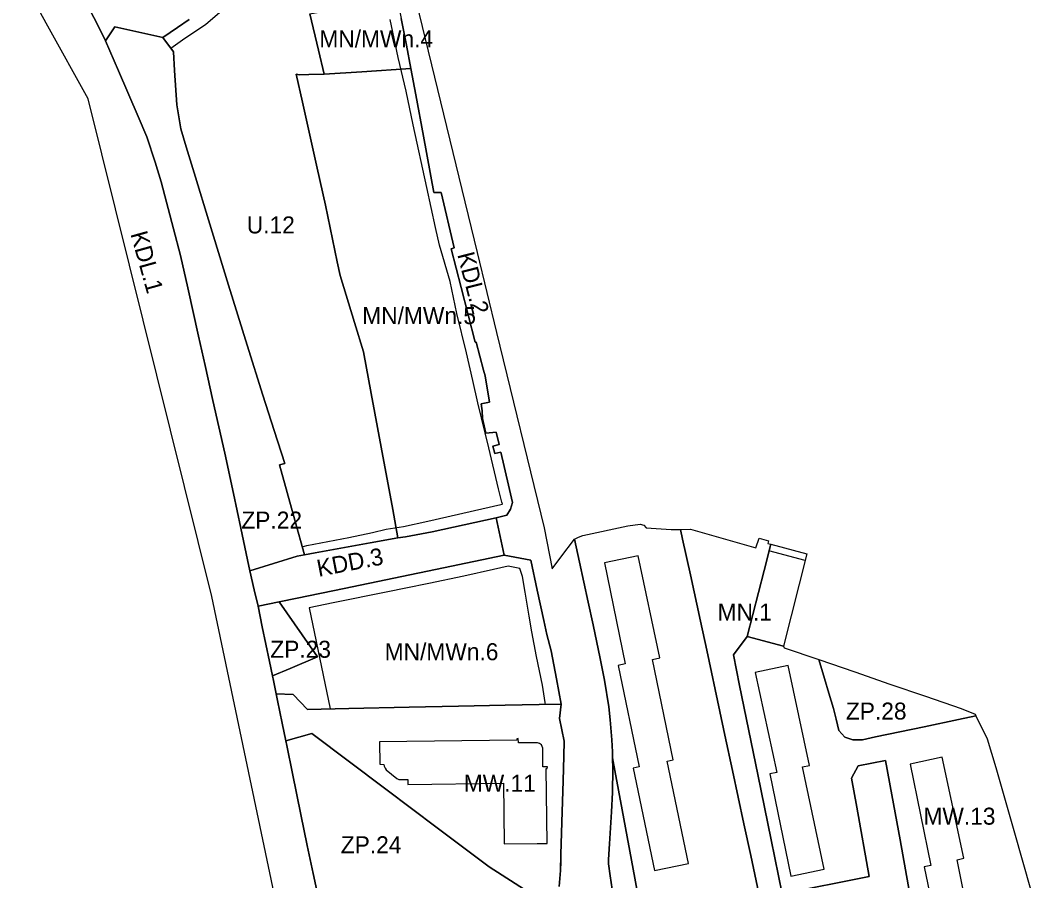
# Model space of a CAD drawing. Extents: x 7429178 to 7430831, y 5550228 to 5551611.
# Drawn here: x 7430377.4 to 7430676.9, y 5550503.4 to 5550756.2 of the extents above; entities that cross this region are included whole.
import ezdxf

# ---------------------------------------------------------------- set-up
doc = ezdxf.new("R2010")
doc.units = 0
for name, color, linetype in [('linie rozgraniczające', 7, 'Continuous'), ('nieprzekraczalne linie zabudowy', 7, 'Continuous'), ('obowiazujace linie zabudowy', 7, 'Continuous'), ('przeznaczenia terenów', 7, 'Continuous')]:
    doc.layers.add(name, color=color, linetype=linetype)

msp = doc.modelspace()

# ---------------------------------------------------------------- linework, layer by layer
at = {"layer": 'linie rozgraniczające'}
for points in [[(7430478.4, 5550824.47), (7430511.65, 5550687.91), (7430517.35, 5550664.42), (7430531.31, 5550607.07), (7430533.69, 5550595), (7430536.22, 5550598.38), (7430540.21, 5550603.72), (7430541.68, 5550596.95), (7430544.25, 5550585.16), (7430545.68, 5550578.56), (7430547.8, 5550568.63), (7430549.01, 5550562.26), (7430550.3, 5550554.42), (7430550.7, 5550550.58), (7430551.26, 5550544.73), (7430551.38, 5550541.18), (7430551.44, 5550539.39), (7430551.55, 5550536.16), (7430551.41, 5550529.27), (7430551.11, 5550523.58), (7430550.49, 5550514.19), (7430550.19, 5550509.57), (7430550.19, 5550508.29), (7430550.71, 5550504.77), (7430552.17, 5550494.96)], [(7430468.65, 5550420.22), (7430433.65, 5550586.89), (7430397.29, 5550733.08), (7430385.48, 5550754.46), (7430377.38, 5550769.13)], [(7430396.56, 5550761.69), (7430400.16, 5550754.72), (7430402.35, 5550750.18), (7430406.18, 5550741.33), (7430411.99, 5550727.94), (7430414.59, 5550721.94), (7430416.99, 5550714.47), (7430418.76, 5550708.67), (7430422.39, 5550694.93), (7430424.48, 5550687.04), (7430426.6, 5550677.54), (7430429.76, 5550663.37), (7430431.7, 5550654.69), (7430433.97, 5550644.49), (7430437.43, 5550628.97), (7430439.99, 5550617.16), (7430442.17, 5550606.9), (7430444.13, 5550597.65), (7430444.82, 5550594.42), (7430446.12, 5550588.84), (7430447.24, 5550583.97), (7430448.49, 5550577.94), (7430450.58, 5550567.76), (7430451.45, 5550563.5), (7430451.73, 5550562.16), (7430452.54, 5550558.21), (7430452.92, 5550556.32), (7430454.29, 5550549.66), (7430455.35, 5550544.48), (7430455.65, 5550543.04), (7430457.33, 5550534.86), (7430459.8, 5550522.83), (7430461.71, 5550513.7), (7430463.47, 5550505.4), (7430464.81, 5550499.08)], [(7430427.01, 5550756.46), (7430423.57, 5550754.1), (7430419.28, 5550751.16), (7430411.3, 5550752.92), (7430405.1, 5550754.28), (7430402.35, 5550750.18), (7430400.16, 5550754.72), (7430396.56, 5550761.69)], [(7430462.49, 5550758.04), (7430465.03, 5550747.36), (7430466.68, 5550740.4), (7430462.15, 5550740.28), (7430459.37, 5550740.2), (7430458.46, 5550740.36), (7430460.3, 5550732.13), (7430464.64, 5550712.76), (7430467.04, 5550701.83), (7430470.5, 5550685.21), (7430471.33, 5550681.21), (7430475.6, 5550667.38), (7430478.27, 5550658.76), (7430480.52, 5550646.52), (7430483.44, 5550630.69), (7430486.81, 5550612.39), (7430488.34, 5550604.1), (7430480.17, 5550602.61), (7430464, 5550599.66), (7430460.85, 5550599.08), (7430458.06, 5550609.24), (7430453.58, 5550625.56), (7430455.08, 5550625.97), (7430452.01, 5550635.62), (7430448.68, 5550646.06), (7430444.03, 5550660.67), (7430438.53, 5550678.33), (7430432.64, 5550697.54), (7430428.84, 5550710.05), (7430426.15, 5550718.97), (7430424.55, 5550724.27), (7430423.33, 5550731.34), (7430422.71, 5550741.46), (7430422.38, 5550746.91), (7430419.28, 5550751.16), (7430423.57, 5550754.1), (7430427.01, 5550756.46)], [(7430535.7, 5550501.67), (7430536.13, 5550506.36), (7430536.26, 5550511.03), (7430536.53, 5550520.54), (7430536.88, 5550532.69), (7430537.08, 5550539.94), (7430537.21, 5550544.36), (7430535.87, 5550551.02), (7430536.32, 5550555.24), (7430534.96, 5550562.62), (7430533.43, 5550570.89), (7430532.12, 5550575.7), (7430531.24, 5550579.75), (7430529.31, 5550588.7), (7430527.4, 5550597.51), (7430519.55, 5550598.95), (7430517.23, 5550609.97), (7430520.35, 5550610.71), (7430521.4, 5550612.48), (7430522.03, 5550614.5), (7430520.85, 5550619.57), (7430518.6, 5550629.24), (7430516.86, 5550628.84), (7430516.19, 5550631.08), (7430518.07, 5550631.5), (7430517.2, 5550635.15), (7430514.16, 5550634.88), (7430513.22, 5550639.18), (7430513.08, 5550641.4), (7430512.78, 5550643.44), (7430515.22, 5550644), (7430513.96, 5550651.7), (7430513.53, 5550653.36), (7430511.37, 5550661.56), (7430511.03, 5550661.61), (7430506.97, 5550677.67), (7430504.02, 5550688.98), (7430504.91, 5550689.27), (7430501.09, 5550705.58), (7430498.94, 5550705.56), (7430495.87, 5550722.14), (7430493.61, 5550734.25), (7430492.17, 5550742), (7430490.84, 5550748.89), (7430489.32, 5550756.73)], [(7430560.26, 5550491.64), (7430557.97, 5550504.04), (7430554.26, 5550524.12), (7430552.13, 5550535.68), (7430551.44, 5550539.39), (7430551.38, 5550541.18), (7430551.26, 5550544.73), (7430550.7, 5550550.58), (7430550.3, 5550554.42), (7430549.01, 5550562.26), (7430547.8, 5550568.63), (7430545.68, 5550578.56), (7430544.25, 5550585.16), (7430541.68, 5550596.95), (7430540.21, 5550603.72), (7430541.39, 5550604.33), (7430542.71, 5550604.75), (7430555.96, 5550607.64), (7430559.56, 5550608.06), (7430560.63, 5550607.8), (7430561.3, 5550607.02), (7430568.68, 5550606.53), (7430571.38, 5550606.58), (7430571.95, 5550603.72), (7430574.32, 5550593.17), (7430577.32, 5550579.59), (7430579.14, 5550571.07), (7430583, 5550553.01), (7430584.47, 5550546.14), (7430586.69, 5550535.76), (7430590.04, 5550520.06), (7430592.03, 5550510.75), (7430594.82, 5550497.67)], [(7430594.82, 5550497.67), (7430592.03, 5550510.75), (7430590.04, 5550520.06), (7430586.69, 5550535.76), (7430584.47, 5550546.14), (7430583, 5550553.01), (7430579.14, 5550571.07), (7430577.32, 5550579.59), (7430574.32, 5550593.17), (7430571.95, 5550603.72), (7430571.38, 5550606.58), (7430574.31, 5550606.64), (7430593.58, 5550601.17), (7430594.48, 5550603.96), (7430597.26, 5550603.21), (7430597.08, 5550602.47), (7430597.91, 5550602.24), (7430595.95, 5550594.49), (7430591.03, 5550575.1), (7430586.94, 5550569.68), (7430588.78, 5550560.69), (7430594.11, 5550534.56), (7430598.03, 5550515.34), (7430601.27, 5550499.45), (7430626.83, 5550504.54), (7430623.19, 5550524.95), (7430621.67, 5550533.46), (7430623.58, 5550537.09), (7430631.64, 5550538.62), (7430633.49, 5550528.54), (7430635.91, 5550515.35), (7430639.07, 5550497.75)], [(7430639.07, 5550497.75), (7430635.91, 5550515.35), (7430633.49, 5550528.54), (7430631.64, 5550538.62), (7430623.58, 5550537.09), (7430621.67, 5550533.46), (7430623.19, 5550524.95), (7430626.83, 5550504.54), (7430601.27, 5550499.45), (7430598.03, 5550515.34), (7430594.11, 5550534.56), (7430588.78, 5550560.69), (7430586.94, 5550569.68), (7430591.03, 5550575.1), (7430601.64, 5550572.22), (7430601.89, 5550571.75), (7430612.06, 5550568.29), (7430613.72, 5550562.8), (7430615.03, 5550558.44), (7430616.39, 5550553.93), (7430617.19, 5550550.8), (7430617.94, 5550547.43), (7430619.72, 5550545.56), (7430622.08, 5550544.75), (7430624.86, 5550544.75), (7430628.74, 5550545.58), (7430642.96, 5550548.59), (7430653.1, 5550550.69), (7430658.24, 5550551.75), (7430661.5, 5550545.06), (7430664.07, 5550536.64), (7430667.02, 5550526.29), (7430669.36, 5550518.12), (7430676.94, 5550491.5)], [(7430526.65, 5550500.05), (7430515.17, 5550507.41), (7430499.88, 5550518.87), (7430484.79, 5550530.19), (7430463.03, 5550546.59), (7430455.35, 5550544.48), (7430454.29, 5550549.66), (7430452.92, 5550556.32), (7430452.54, 5550558.21), (7430452.54, 5550558.21), (7430457.55, 5550558.05), (7430461.75, 5550553.67), (7430473.94, 5550553.93), (7430491.6, 5550554.3), (7430506.11, 5550554.6), (7430519.87, 5550554.89), (7430529.82, 5550555.1), (7430536.32, 5550555.24), (7430535.87, 5550551.02), (7430537.21, 5550544.36), (7430537.08, 5550539.94), (7430536.88, 5550532.69), (7430536.53, 5550520.54), (7430536.26, 5550511.03), (7430536.2, 5550508.88), (7430536.13, 5550506.36), (7430535.7, 5550501.67)], [(7430464.81, 5550499.08), (7430463.47, 5550505.4), (7430461.71, 5550513.7), (7430459.8, 5550522.83), (7430457.33, 5550534.86), (7430455.65, 5550543.04), (7430455.35, 5550544.48), (7430463.03, 5550546.59), (7430484.79, 5550530.19), (7430499.88, 5550518.87), (7430515.17, 5550507.41), (7430526.65, 5550500.05)], [(7430552.17, 5550494.96), (7430550.71, 5550504.77), (7430550.19, 5550508.29), (7430550.19, 5550509.57), (7430550.49, 5550514.19), (7430551.11, 5550523.58), (7430551.41, 5550529.27), (7430551.55, 5550536.16), (7430551.44, 5550539.39), (7430552.13, 5550535.68), (7430554.26, 5550524.12), (7430557.97, 5550504.04), (7430560.26, 5550491.64)]]:
    msp.add_lwpolyline(points, dxfattribs=at)
for points in [[(7430477.72, 5550741.09), (7430466.68, 5550740.4), (7430465.03, 5550747.36), (7430462.49, 5550758.04), (7430467.74, 5550759.02), (7430480.48, 5550761.37), (7430488.15, 5550762.79), (7430489.32, 5550756.73), (7430490.84, 5550748.89), (7430492.17, 5550742)], [(7430419.28, 5550751.16), (7430422.38, 5550746.91), (7430422.71, 5550741.46), (7430423.33, 5550731.34), (7430424.55, 5550724.27), (7430426.15, 5550718.97), (7430428.84, 5550710.05), (7430432.64, 5550697.54), (7430438.53, 5550678.33), (7430444.03, 5550660.67), (7430448.68, 5550646.06), (7430452.01, 5550635.62), (7430455.08, 5550625.97), (7430453.58, 5550625.56), (7430458.06, 5550609.24), (7430460.85, 5550599.08), (7430460.85, 5550599.08), (7430458.69, 5550598.69), (7430451.78, 5550596.56), (7430444.82, 5550594.42), (7430444.13, 5550597.65), (7430442.17, 5550606.9), (7430439.99, 5550617.16), (7430437.43, 5550628.97), (7430433.97, 5550644.49), (7430431.7, 5550654.69), (7430429.76, 5550663.37), (7430426.6, 5550677.54), (7430424.48, 5550687.04), (7430422.39, 5550694.93), (7430418.76, 5550708.67), (7430416.99, 5550714.47), (7430414.59, 5550721.94), (7430411.99, 5550727.94), (7430406.18, 5550741.33), (7430402.35, 5550750.18), (7430405.1, 5550754.28), (7430411.3, 5550752.92)], [(7430466.68, 5550740.4), (7430477.72, 5550741.09), (7430492.17, 5550742), (7430493.61, 5550734.25), (7430495.87, 5550722.14), (7430498.94, 5550705.56), (7430501.09, 5550705.58), (7430504.91, 5550689.27), (7430504.02, 5550688.98), (7430506.97, 5550677.67), (7430511.03, 5550661.61), (7430511.37, 5550661.56), (7430513.53, 5550653.36), (7430513.96, 5550651.7), (7430515.22, 5550644), (7430512.78, 5550643.44), (7430513.08, 5550641.4), (7430513.22, 5550639.18), (7430514.16, 5550634.88), (7430517.2, 5550635.15), (7430518.07, 5550631.5), (7430516.19, 5550631.08), (7430516.86, 5550628.84), (7430518.6, 5550629.24), (7430520.85, 5550619.57), (7430522.03, 5550614.5), (7430521.4, 5550612.48), (7430520.35, 5550610.71), (7430517.23, 5550609.97), (7430498.42, 5550605.9), (7430490.61, 5550604.34), (7430488.34, 5550604.1), (7430486.81, 5550612.39), (7430483.44, 5550630.69), (7430480.52, 5550646.52), (7430478.27, 5550658.76), (7430475.6, 5550667.38), (7430471.33, 5550681.21), (7430470.5, 5550685.21), (7430467.04, 5550701.83), (7430464.64, 5550712.76), (7430460.3, 5550732.13), (7430458.46, 5550740.36), (7430459.37, 5550740.2), (7430462.15, 5550740.28)], [(7430519.55, 5550598.95), (7430501.75, 5550595.26), (7430472.59, 5550589.22), (7430458.71, 5550586.35), (7430453.46, 5550585.27), (7430453.42, 5550585.26), (7430447.24, 5550583.97), (7430446.12, 5550588.84), (7430444.82, 5550594.42), (7430451.78, 5550596.56), (7430458.69, 5550598.69), (7430460.85, 5550599.08), (7430460.85, 5550599.08), (7430464, 5550599.66), (7430480.17, 5550602.61), (7430488.34, 5550604.1), (7430490.61, 5550604.34), (7430498.42, 5550605.9), (7430517.23, 5550609.97)], [(7430601.64, 5550572.22), (7430591.03, 5550575.1), (7430595.95, 5550594.49), (7430597.91, 5550602.24), (7430608.53, 5550599.38)], [(7430536.32, 5550555.24), (7430529.82, 5550555.1), (7430519.87, 5550554.89), (7430506.11, 5550554.6), (7430491.6, 5550554.3), (7430473.94, 5550553.93), (7430461.75, 5550553.67), (7430457.55, 5550558.05), (7430452.54, 5550558.21), (7430452.54, 5550558.21), (7430451.73, 5550562.16), (7430451.45, 5550563.5), (7430456.66, 5550565.69), (7430464.73, 5550569.09), (7430457.92, 5550578.86), (7430453.46, 5550585.27), (7430453.46, 5550585.27), (7430458.71, 5550586.35), (7430472.59, 5550589.22), (7430501.75, 5550595.26), (7430519.55, 5550598.95), (7430527.4, 5550597.51), (7430529.31, 5550588.7), (7430531.24, 5550579.75), (7430532.12, 5550575.7), (7430533.43, 5550570.89), (7430534.96, 5550562.62)], [(7430456.66, 5550565.69), (7430451.45, 5550563.5), (7430450.58, 5550567.76), (7430448.49, 5550577.94), (7430447.24, 5550583.97), (7430453.42, 5550585.26), (7430453.46, 5550585.27), (7430453.46, 5550585.27), (7430457.92, 5550578.86), (7430464.73, 5550569.09)], [(7430658.24, 5550551.75), (7430653.1, 5550550.69), (7430642.96, 5550548.59), (7430628.74, 5550545.58), (7430624.86, 5550544.75), (7430622.08, 5550544.75), (7430619.72, 5550545.56), (7430617.94, 5550547.43), (7430617.19, 5550550.8), (7430616.39, 5550553.93), (7430615.03, 5550558.44), (7430613.72, 5550562.8), (7430612.06, 5550568.29), (7430622.61, 5550564.7), (7430632.92, 5550561.09), (7430643.38, 5550557.53), (7430653.88, 5550553.94), (7430657.99, 5550552.25)]]:
    msp.add_lwpolyline(points, close=True, dxfattribs=at)
at = {"layer": 'nieprzekraczalne linie zabudowy'}
for points in [[(7430440.13, 5550762.04), (7430431.8, 5550754.82), (7430425.76, 5550750.82), (7430421.64, 5550747.93)], [(7430460.19, 5550601.49), (7430461.57, 5550601.79), (7430473.94, 5550604.23), (7430480.9, 5550605.64), (7430484.91, 5550606.61), (7430490.01, 5550607.47), (7430497.09, 5550609.02), (7430512.97, 5550612.61), (7430518.58, 5550613.93), (7430518.94, 5550614.01), (7430519.05, 5550614.12), (7430518.93, 5550614.55), (7430517.92, 5550618.52), (7430515.06, 5550630.57), (7430511.84, 5550643.77), (7430510.32, 5550650.37), (7430508.5, 5550658.46), (7430505.63, 5550670.05), (7430503.67, 5550679.42), (7430500.56, 5550690.11), (7430499.36, 5550695.33), (7430496.85, 5550707.07), (7430492.84, 5550725.45), (7430490.74, 5550735.34), (7430488.44, 5550745.28), (7430486.02, 5550756.44)], [(7430608.01, 5550597.45), (7430597.39, 5550600.31)], [(7430531.73, 5550555.14), (7430531.66, 5550555.7), (7430530.79, 5550560.79), (7430529.09, 5550569.18), (7430527.67, 5550576.49), (7430526.9, 5550581.07), (7430525.71, 5550588.15), (7430524.94, 5550592.7), (7430524.18, 5550595.07), (7430520.72, 5550595.76), (7430516.4, 5550594.8), (7430507.74, 5550592.86), (7430497.41, 5550590.68), (7430490.67, 5550589.29), (7430485.42, 5550588.23), (7430469.34, 5550585.01), (7430462.23, 5550583.53), (7430468.44, 5550553.81)]]:
    msp.add_lwpolyline(points, dxfattribs=at)
at = {"layer": 'obowiazujace linie zabudowy'}
for points in [[(7430558.95, 5550598.81), (7430549.07, 5550596.78), (7430555.16, 5550567.06), (7430553.06, 5550566.62), (7430559.25, 5550536.77), (7430557.52, 5550536.41), (7430563.72, 5550506.31), (7430573.74, 5550508.4), (7430567.45, 5550538.46), (7430569.27, 5550538.82), (7430563.2, 5550568.34), (7430565.31, 5550568.79), (7430558.95, 5550598.81)], [(7430613.62, 5550506.71), (7430607.26, 5550536.75), (7430609.34, 5550537.21), (7430603.04, 5550566.56), (7430593.38, 5550564.54), (7430599.67, 5550535.16), (7430597.65, 5550534.72), (7430603.84, 5550504.69), (7430613.62, 5550506.71)], [(7430482.92, 5550544.17), (7430483.01, 5550537.56), (7430484.19, 5550537.44), (7430484.25, 5550537.01), (7430484.55, 5550536.36), (7430484.92, 5550535.94), (7430488.06, 5550533.33), (7430488.62, 5550533.05), (7430491.21, 5550533.09), (7430491.24, 5550531.6), (7430519.38, 5550532.03), (7430519.59, 5550514.13), (7430529.28, 5550514.22), (7430532.25, 5550514.28), (7430531.89, 5550536.26), (7430532.24, 5550536.3), (7430532.26, 5550536.82), (7430530.96, 5550536.78), (7430530.91, 5550542.31), (7430530.5, 5550543.22), (7430529.97, 5550543.65), (7430529.34, 5550543.85), (7430523.76, 5550543.83), (7430523.73, 5550545.08), (7430523.27, 5550545.06), (7430523.29, 5550544.64), (7430482.92, 5550544.17)], [(7430648.28, 5550539.64), (7430638.89, 5550537.58), (7430644.92, 5550507.82), (7430642.96, 5550507.39), (7430649.21, 5550477.72), (7430658.7, 5550479.62), (7430652.68, 5550509.5), (7430654.69, 5550509.93), (7430648.28, 5550539.64)]]:
    msp.add_lwpolyline(points, dxfattribs=at)

# ---------------------------------------------------------------- texts
at = {"layer": 'przeznaczenia terenów'}
for s, p in [('MN/MWn.4', (7430465.25, 5550748.22)), ('U.12', (7430443.92, 5550693.55)), ('MN/MWn.5', (7430477.86, 5550666.89)), ('ZP.22', (7430442.32, 5550606.8)), ('MN.1', (7430582.29, 5550579.79)), ('ZP.23', (7430450.83, 5550568.85)), ('MN/MWn.6', (7430484.45, 5550568.12)), ('ZP.28', (7430620, 5550550.68)), ('MW.11', (7430507.7, 5550529.46)), ('MW.13', (7430642.79, 5550519.79)), ('ZP.24', (7430471.54, 5550511.39))]:
    msp.add_text(s, height=5, dxfattribs=at).set_placement(p)
for s, rotation, p in [('KDL.1', 285.586, (7430409.69, 5550693.44)), ('KDL.2', 284.4038, (7430505.76, 5550687.38)), ('KDD.3', 10.8763, (7430465.03, 5550592.62))]:
    msp.add_text(s, height=5, rotation=rotation, dxfattribs=at).set_placement(p)

doc.saveas('drawing.dxf')
